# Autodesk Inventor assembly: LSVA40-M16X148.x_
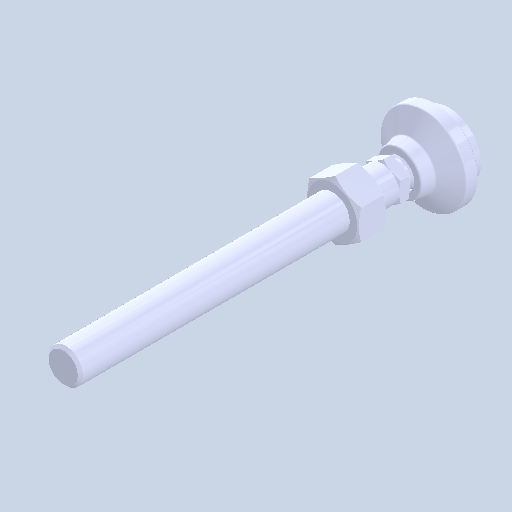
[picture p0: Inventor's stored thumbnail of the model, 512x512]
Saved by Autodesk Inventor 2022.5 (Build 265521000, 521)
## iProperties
Created: 2024-08
Part Number: LSVA40-M16X148.x_
Document SubType Name: Assembly
Designer: ImaoCorp
Author: ImaoCorp
Sending System: SOLIDWORKS 2022-2022290
MC: AMD64
MC_MODEL: Intel64 Family 6 Model 60 Stepping 3, GenuineIntel
OS: Windows_NT
FRU: Parasolid Version 33.1, build 260,  4-25-2022
FORMAT: text
GUISE: transmit
KEY: FILELSVA40-M16X148.x_t
DATE: Fri Aug 23 16:07:43 2024
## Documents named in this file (4)
- X:\14_SW2022-Inv2022\06_2024-10新製品(SME)\ELS_データ\l\lsva40-m16x148\LSVA40-M16X148.x_.iam
- X:\14_SW2022-Inv2022\06_2024-10新製品(SME)\ELS_データ\l\lsva40-m16x148\LSVA40-M16X148_01.ipt
- X:\14_SW2022-Inv2022\06_2024-10新製品(SME)\ELS_データ\l\lsva40-m16x148\LSVA40-M16X148_02.ipt
- X:\14_SW2022-Inv2022\06_2024-10新製品(SME)\ELS_データ\l\lsva40-m16x148\LSVA40-M16X148_03.ipt
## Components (3 placed, 3 different names)
1. LSVA40-M16X148_01
2. LSVA40-M16X148_02
3. LSVA40-M16X148_03
